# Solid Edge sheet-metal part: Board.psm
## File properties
Author: conerly
Template: ansi sheet metal.psm
Last saved by: jccrumbl
Revision: 36
Application: Solid Edge
Density: 0.0979772159 lbm/in^3
Accuracy: 0.990
Material Thickness: 0.125 in
Bend Radius: 0.125 in
Relief Width: 0.125 in
Relief Length: 0.125 in
Neutral Factor: 0.330
Minimum Arc Length: 0.005 in
Deviational Tolerance: 0.005 in
Material: Aluminum, 1060
Face Style: Aluminum
Fill Style: ANSI38(Aluminum)
Virtual Style: Polished aluminum
Coef. of Thermal Exp: 2.3e-05
Thermal Conductivity: 221.0
Specific Heat: 920.0
Modulus of Elasticity: 68947570000.0
Poisson's Ratio: 0.33
Yield Stress: 27579028.0
Ultimate Stress: 68947570.0
Elongation: 0.0
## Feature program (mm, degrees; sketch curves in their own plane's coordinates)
base tab "unnamed BaseTab 1"
flange "Flange_1"
flange "Flange_2"
flange "Flange_3"
flange "Flange_4"
sketch for "Hole_1" plane through (3.175, -609.6, -106.3625) normal (0, -1, 0) x-axis (1, 0, 0)
hole "Hole_1"
sketch for "Hole_2" plane through (-114.3, 76.2, 3.175) normal (0, 0, 1) x-axis (1, 0, 0)
  hole centre (-610.1736, -610.1736) bore radius 19.05
hole "Hole_2"
flange "Flange_5"
flange "Flange_6"
sketch for "ExtrudedCutout_1" plane through (-114.3, 76.2, 3.175) normal (0, 0, 1) x-axis (1, 0, 0)
  bspline degree 3 poles (436.562, 570.0215) (486.4885, 470.1611) (389.4528, 372.6415) (482.4301, 258.6885) (397.7229, 116.5915) (315.6476, -65.3133) (162.5598, -198.8693) (149.5108, -439.8004) (-78.2215, -425.8414) (-102.2775, -631.9981) (-190.9565, -696.0843) (-244.9824, -747.1203) knots 0 0.1107 0.2088 0.3073 0.4167 0.5753 0.6742 0.7905 0.8747 1 multiplicities 4 1 1 1 1 1 1 1 1 4
extrude "ExtrudedCutout_1" cut
sketch for "Hole_3" plane through (-1195.3875, -766.7625, -3.175) normal (0, 0, 1) x-axis (1, 0, 0)
  hole centre (-12.0699, 58.9703) bore radius 19.05
hole "Hole_3"
sketch for "Hole_4" plane through (-911.225, -766.7625, -109.5375) normal (1, 0, 0) x-axis (0, 1, 0)
  hole centre (91.6071, 44.1237) bore radius 19.05
hole "Hole_4"
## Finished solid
Body 1: solid body, 48 faces, 126 edges, 76 vertices.
  Faces by surface: plane 31, cylinder 16, swept 1
  Edges by curve: line 91, circle 30, spline 3, intersection 2
Bounding box of the edges (mm; curved faces can reach further): 1823.350 x 1682.750 x 396.875, from (-1479.55, -920.75, -209.55) to (343.7999, 762, 187.325).
Cylindrical faces by radius (mm): R3.175 x6, R6.35 x6, R19.05 x4
Planar faces by outward normal: +x 4, +y 6, +z 6, -x 7, -y 5, -z 3
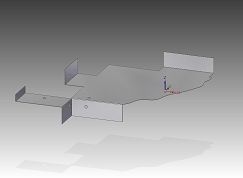
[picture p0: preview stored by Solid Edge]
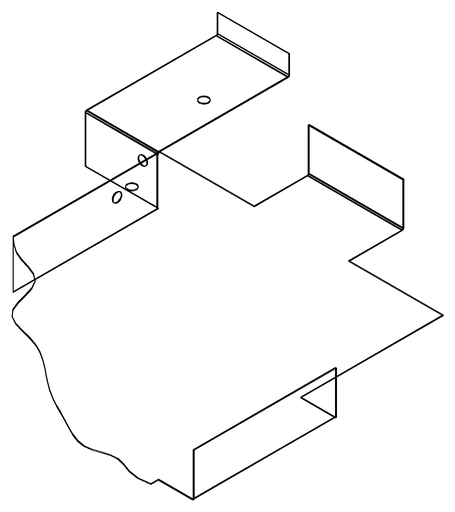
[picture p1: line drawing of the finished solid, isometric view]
